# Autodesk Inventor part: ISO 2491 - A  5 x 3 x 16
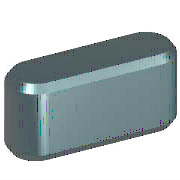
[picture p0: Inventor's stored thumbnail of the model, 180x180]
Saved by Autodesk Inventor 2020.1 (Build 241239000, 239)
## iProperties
Created: 2019-01
Part Number: ISO 2491 - A  5 x 3 x 16
Material: Stahl, weich
Description: Passfedern
Document SubType Name: Modeling
Standard: ISO 2491
Designer: lutzd
Standard Revision: First edition 1974-08-15
Standards Organization: ISO
Language: de-DE
Size Designation: A  5 x 3 x 16
Categories: <MemberInstance><Categories><Category DisplayName="Wellenteile" InternalName="7f7aeb1f-a693-4053-b835-cee3144e0d98" Mnemonic="SHFT"><Category DisplayName="Passf
Mass: 1.71134 g
Surface Area: 2.44306 cm^2
Volume: 0.218006 cm^3
Density: 7.85 g/cm^3
Appearance: Halbpoliert
IsCustomPart: 0
Author: lutzd
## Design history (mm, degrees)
workplane "Work Plane1"
workplane "Work Plane2"
sketch "Skizze1"
  geometry: L1 (2.5, 2.5)-(13.5, 2.5); L2 (13.5, -2.5)-(2.5, -2.5); L3 (0, 9.4)-(0, -7.4) reference; L4 (-5, 0)-(30, 0) reference; L5 (16, 0)-(16, 7); A1 r 2.5 centre (2.5, 0) between (2.5, 2.5) and (2.5, -2.5); A2 r 2.5 centre (13.5, 0) between (13.5, -2.5) and (13.5, 2.5)
  constraints: 6 end point, 5 point on circle, 4 tangent, 3 point on line, 2 centre point, 1 horizontal, 1 parallel, 1 perpendicular
  dimensions: "d0" = 2.5 radius of A1 (= 0.5 x PB); "d13" = 2.5 radius of A2 (= 0.5 x PB); "d14" = 16 distance between parallel lines of L5 L3 (= NLG)
extrude "Körper1" new body sketch "Skizze1" taper "d3" = 0 deg; stored distance "d4" = 10
workplane "Work Plane3"
body "Solid1"
chamfer "Fase1" distance "d8" = 0.4 (= PHH); stored, may be unused: second distance "d9" = 0.4 (= PHH), angle "d15" = 45 deg
other parameters: "d1" = -1.8 (= -PNT), "d2" = 1.2 (= PH - PNT), "NLG" = 16 [user parameter; used in 1 equation term], "PB" = 5 [user parameter; used in 2 equation terms], "PNT" = 1.8 [user parameter; used in 2 equation terms], "PH" = 3 [user parameter; used in 1 equation term], "PHH" = 0.4 [user parameter; used in 2 equation terms], "d10" = 0, "d16" = 0, "d17" = 0, "d18" = 0, "RR" = 0.16 [user parameter], "WDMIN" = 12 [user parameter], "WDMAX" = 17 [user parameter], "PLB1" = 16 [user parameter], "PLB2" = 16 [user parameter], "PUEB" = 1.4 [user parameter]
